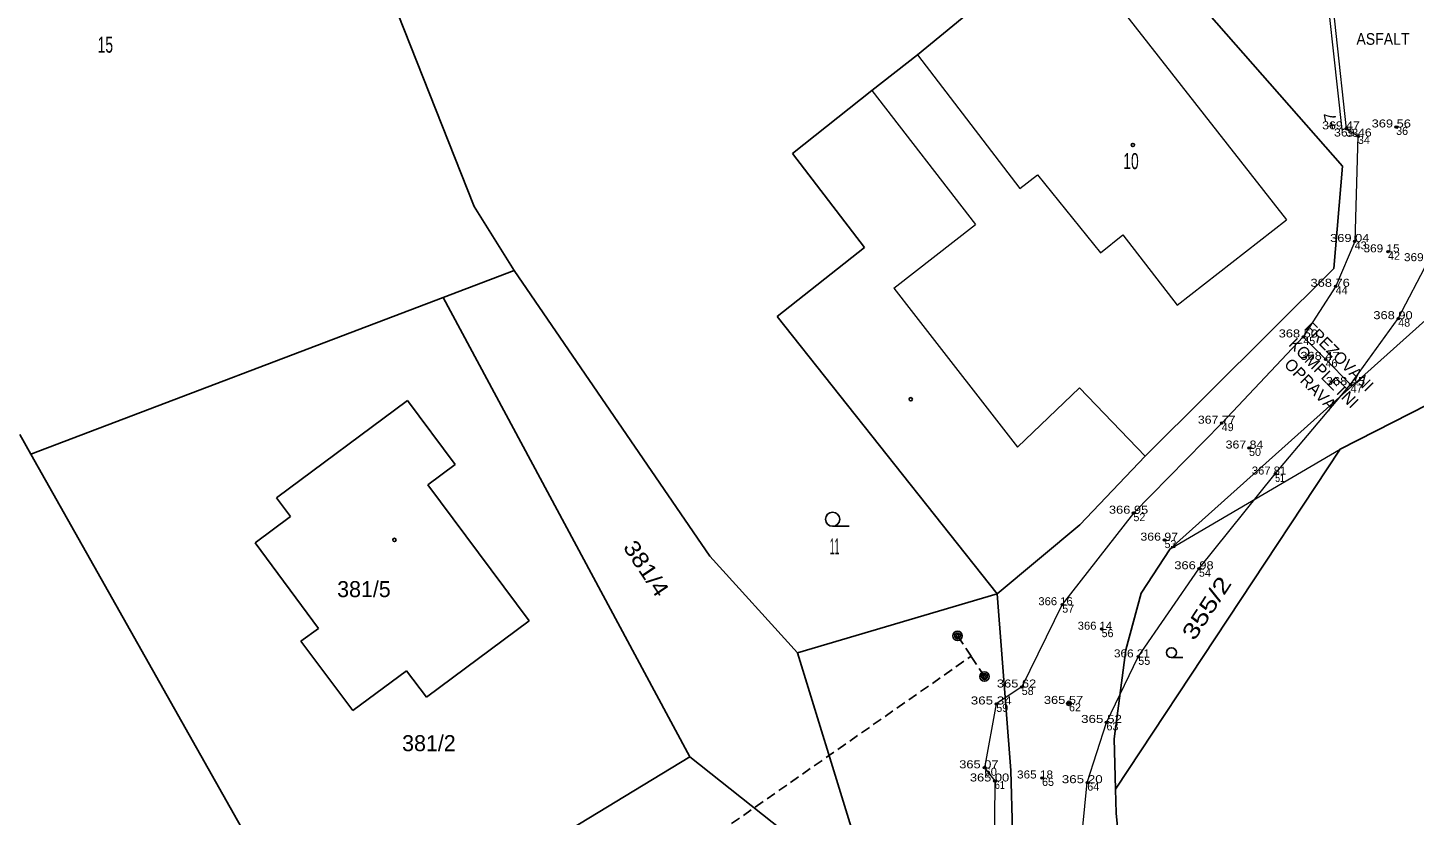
# Model space of a CAD drawing. Extents: x -592965 to -592390, y -1145071 to -1144631.
# Drawn here: x -592704.9 to -592631.3, y -1144835.7 to -1144793.9 of the extents above; entities that cross this region are included whole.
import ezdxf
from ezdxf.enums import TextEntityAlignment as Align

# ---------------------------------------------------------------- set-up
doc = ezdxf.new("R2010")
doc.units = 0
doc.header["$LTSCALE"] = 0.17
doc.header["$PDMODE"] = 32
doc.header["$PDSIZE"] = 0.085
doc.linetypes.add('MEDIUM_DASHED', pattern=[4.5, 3, -1.5])
for name, color, linetype, lineweight in [('1', 7, 'Continuous', 13), ('3', 7, 'Continuous', 13), ('4', 7, 'Continuous', 25)]:
    doc.layers.add(name, color=color, linetype=linetype, lineweight=lineweight)
doc.layers.add('2', color=7, linetype='Continuous')

msp = doc.modelspace()

# ---------------------------------------------------------------- linework, layer by layer
at = {"layer": '1'}
msp.add_line((-592635.14, -1144799.25), (-592634.9, -1144799.22), dxfattribs=at)
for points in [[(-592637.31, -1144779.29), (-592636.24, -1144789.11), (-592635.14, -1144799.25)], [(-592637.07, -1144779.26), (-592636, -1144789.08), (-592634.9, -1144799.22)], [(-592634.9, -1144799.22), (-592634.28, -1144799.6), (-592634.45, -1144805.2), (-592635.46, -1144807.58), (-592637.18, -1144810.27), (-592641.51, -1144814.85)], [(-592641.79, -1144908.72), (-592641.16, -1144902.38), (-592640.38, -1144895.02), (-592640.15, -1144889.82), (-592640.65, -1144883.36), (-592641.29, -1144877.49), (-592642.3, -1144871.74), (-592643.21, -1144867.79), (-592644.53, -1144861.22), (-592645.89, -1144855.01), (-592647.22, -1144849.42), (-592648.49, -1144841.98), (-592649.04, -1144837.88), (-592648.65, -1144833.94), (-592647.63, -1144830.74), (-592645.94, -1144827.26), (-592642.72, -1144822.58), (-592638.67, -1144817.55), (-592634.67, -1144812.8), (-592632.14, -1144809.3), (-592630.54, -1144806.22), (-592629.58, -1144805.74)], [(-592634.67, -1144812.8), (-592636, -1144811.46), (-592637.18, -1144810.27)], [(-592641.51, -1144814.85), (-592646.2, -1144819.63), (-592649.98, -1144824.49), (-592652.13, -1144828.86), (-592653.48, -1144829.76), (-592654.11, -1144833.15), (-592653.56, -1144833.85), (-592653.59, -1144837.97), (-592653.49, -1144842.34), (-592651.91, -1144850.15)]]:
    msp.add_lwpolyline(points, dxfattribs=at)
msp.add_circle((-592649.62, -1144829.73), 0.125, dxfattribs=at)
at = {"layer": '2'}
for p in [(-592632.25, -1144799.12), (-592634.9, -1144799.22), (-592634.28, -1144799.6), (-592634.45, -1144805.2), (-592632.68, -1144805.75), (-592635.46, -1144807.58), (-592632.14, -1144809.3), (-592637.18, -1144810.27), (-592636, -1144811.46), (-592634.67, -1144812.8), (-592641.51, -1144814.85), (-592640.06, -1144816.17), (-592638.67, -1144817.55), (-592646.2, -1144819.63), (-592644.55, -1144821.06), (-592642.72, -1144822.58), (-592649.98, -1144824.49), (-592647.89, -1144825.79), (-592645.94, -1144827.26), (-592652.13, -1144828.86), (-592653.48, -1144829.76), (-592649.62, -1144829.73), (-592647.63, -1144830.74), (-592654.11, -1144833.15), (-592651.05, -1144833.69), (-592653.56, -1144833.85), (-592648.65, -1144833.94)]:
    msp.add_point(p, dxfattribs=at)
at = {"layer": '3'}
for centre, radius in [((-592632.2501, -1144799.1199), 0.0625), ((-592632.2501, -1144799.1199), 0.0395), ((-592632.2501, -1144799.1199), 0.0125), ((-592634.9001, -1144799.2199), 0.0625), ((-592634.9001, -1144799.2199), 0.0395), ((-592634.9001, -1144799.2199), 0.0125), ((-592634.2801, -1144799.5999), 0.0625), ((-592634.2801, -1144799.5999), 0.0395), ((-592634.2801, -1144799.5999), 0.0125), ((-592634.4501, -1144805.1999), 0.0625), ((-592634.4501, -1144805.1999), 0.0395), ((-592634.4501, -1144805.1999), 0.0125), ((-592632.6801, -1144805.7499), 0.0625), ((-592632.6801, -1144805.7499), 0.0395), ((-592632.6801, -1144805.7499), 0.0125), ((-592635.4601, -1144807.5799), 0.0625), ((-592635.4601, -1144807.5799), 0.0395), ((-592635.4601, -1144807.5799), 0.0125), ((-592632.1401, -1144809.2999), 0.0625), ((-592632.1401, -1144809.2999), 0.0395), ((-592632.1401, -1144809.2999), 0.0125), ((-592637.1801, -1144810.2699), 0.0625), ((-592637.1801, -1144810.2699), 0.0395), ((-592637.1801, -1144810.2699), 0.0125), ((-592636.0001, -1144811.4599), 0.0625), ((-592636.0001, -1144811.4599), 0.0395), ((-592636.0001, -1144811.4599), 0.0125), ((-592634.6701, -1144812.7999), 0.0625), ((-592634.6701, -1144812.7999), 0.0395), ((-592634.6701, -1144812.7999), 0.0125), ((-592641.5101, -1144814.8499), 0.0625), ((-592641.5101, -1144814.8499), 0.0395), ((-592641.5101, -1144814.8499), 0.0125), ((-592640.0601, -1144816.1699), 0.0625), ((-592640.0601, -1144816.1699), 0.0395), ((-592640.0601, -1144816.1699), 0.0125), ((-592638.6701, -1144817.5499), 0.0625), ((-592638.6701, -1144817.5499), 0.0395), ((-592638.6701, -1144817.5499), 0.0125), ((-592646.2001, -1144819.6299), 0.0625), ((-592646.2001, -1144819.6299), 0.0395), ((-592646.2001, -1144819.6299), 0.0125), ((-592644.5501, -1144821.0599), 0.0625), ((-592644.5501, -1144821.0599), 0.0395), ((-592644.5501, -1144821.0599), 0.0125), ((-592642.7201, -1144822.5799), 0.0625), ((-592642.7201, -1144822.5799), 0.0395), ((-592642.7201, -1144822.5799), 0.0125), ((-592649.9801, -1144824.4899), 0.0625), ((-592649.9801, -1144824.4899), 0.0395), ((-592649.9801, -1144824.4899), 0.0125), ((-592647.8901, -1144825.7899), 0.0625), ((-592647.8901, -1144825.7899), 0.0395), ((-592647.8901, -1144825.7899), 0.0125), ((-592645.9401, -1144827.2599), 0.0625), ((-592645.9401, -1144827.2599), 0.0395), ((-592645.9401, -1144827.2599), 0.0125), ((-592652.1301, -1144828.8599), 0.0625), ((-592652.1301, -1144828.8599), 0.0395), ((-592652.1301, -1144828.8599), 0.0125), ((-592653.4801, -1144829.7599), 0.0625), ((-592653.4801, -1144829.7599), 0.0395), ((-592653.4801, -1144829.7599), 0.0125), ((-592649.6201, -1144829.7299), 0.0625), ((-592649.6201, -1144829.7299), 0.0395), ((-592649.6201, -1144829.7299), 0.0125), ((-592647.6301, -1144830.7399), 0.0625), ((-592647.6301, -1144830.7399), 0.0395), ((-592647.6301, -1144830.7399), 0.0125), ((-592654.1101, -1144833.1499), 0.0625), ((-592654.1101, -1144833.1499), 0.0395), ((-592654.1101, -1144833.1499), 0.0125), ((-592651.0501, -1144833.6899), 0.0625), ((-592651.0501, -1144833.6899), 0.0395), ((-592651.0501, -1144833.6899), 0.0125), ((-592653.5601, -1144833.8499), 0.0625), ((-592653.5601, -1144833.8499), 0.0395), ((-592653.5601, -1144833.8499), 0.0125), ((-592648.6501, -1144833.9399), 0.0625), ((-592648.6501, -1144833.9399), 0.0395), ((-592648.6501, -1144833.9399), 0.0125)]:
    msp.add_circle(centre, radius, dxfattribs=at)
at = {"layer": '4'}
for p, q in [((-592657.67, -1144795.29), (-592649.93, -1144788.92)), ((-592685.87, -1144791.57), (-592681.2, -1144803.34)), ((-592660.09, -1144797.18), (-592657.67, -1144795.29)), ((-592664.31, -1144800.54), (-592660.09, -1144797.18)), ((-592664.31, -1144800.54), (-592660.48, -1144805.53)), ((-592635.55, -1144806.64), (-592635.1, -1144801.2)), ((-592681.2, -1144803.34), (-592679.08, -1144806.74)), ((-592665.11, -1144809.19), (-592660.48, -1144805.53)), ((-592682.86, -1144808.18), (-592679.08, -1144806.74)), ((-592679.08, -1144806.74), (-592668.69, -1144821.92)), ((-592645.57, -1144816.6), (-592635.55, -1144806.64)), ((-592704.74, -1144816.49), (-592682.86, -1144808.18)), ((-592682.86, -1144808.18), (-592671.64, -1144829.05)), ((-592665.11, -1144809.19), (-592653.43, -1144823.92)), ((-592644.25, -1144821.53), (-592630.7, -1144809.39)), ((-592635.23, -1144816.23), (-592628.66, -1144812.88)), ((-592691.7, -1144818.81), (-592684.75, -1144813.64)), ((-592684.75, -1144813.64), (-592682.21, -1144817.05)), ((-592705.33, -1144815.45), (-592704.74, -1144816.49)), ((-592704.74, -1144816.49), (-592691.02, -1144840.81)), ((-592649.04, -1144820.25), (-592645.57, -1144816.6)), ((-592647.16, -1144834.28), (-592635.23, -1144816.23)), ((-592683.66, -1144818.12), (-592682.21, -1144817.05)), ((-592683.66, -1144818.12), (-592678.29, -1144825.34)), ((-592691.7, -1144818.81), (-592690.96, -1144819.81)), ((-592692.84, -1144821.21), (-592690.96, -1144819.81)), ((-592661.295, -1144820.33), (-592662.17, -1144820.33)), ((-592653.43, -1144823.92), (-592649.04, -1144820.25)), ((-592692.84, -1144821.21), (-592689.47, -1144825.75)), ((-592668.69, -1144821.92), (-592664.03, -1144827.05)), ((-592664.03, -1144827.05), (-592653.43, -1144823.92)), ((-592653.43, -1144823.92), (-592652.71, -1144833.3)), ((-592683.74, -1144829.4), (-592678.29, -1144825.34)), ((-592690.4, -1144826.43), (-592689.47, -1144825.75)), ((-592690.4, -1144826.43), (-592687.64, -1144830.11)), ((-592664.03, -1144827.05), (-592661.12, -1144836.54)), ((-592647.23, -1144831.62), (-592646.61, -1144826.89)), ((-592643.568, -1144827.3), (-592644.18, -1144827.3)), ((-592687.64, -1144830.11), (-592684.79, -1144828)), ((-592684.79, -1144828), (-592683.74, -1144829.4)), ((-592671.64, -1144829.05), (-592669.75, -1144832.57)), ((-592647.23, -1144831.62), (-592647.16, -1144834.28)), ((-592689.08, -1144844.27), (-592669.75, -1144832.57)), ((-592669.75, -1144832.57), (-592663.06, -1144837.87))]:
    msp.add_line(p, q, dxfattribs=at)
at = {"layer": '4', "lineweight": 13}
for p, q in [((-592649.93, -1144788.92), (-592638.07, -1144804.05)), ((-592657.67, -1144795.29), (-592652.24, -1144802.39)), ((-592660.09, -1144797.18), (-592654.58, -1144804.3)), ((-592643.87, -1144808.59), (-592638.07, -1144804.05)), ((-592658.93, -1144807.69), (-592654.58, -1144804.3)), ((-592647.94, -1144805.8), (-592646.77, -1144804.85)), ((-592646.77, -1144804.85), (-592643.87, -1144808.59)), ((-592652.35, -1144816.13), (-592649.07, -1144812.97)), ((-592649.07, -1144812.97), (-592645.57, -1144816.6)), ((-592644.25, -1144821.53), (-592635.23, -1144816.23))]:
    msp.add_line(p, q, dxfattribs=at)
at = {"layer": '4'}
for points in [[(-592647.73, -1144786.83), (-592647.46, -1144787.13), (-592635.1, -1144801.2)], [(-592646.61, -1144826.89), (-592645.79, -1144823.88), (-592644.25, -1144821.53)], [(-592652.71, -1144833.3), (-592652.44, -1144842.96), (-592646.69, -1144839.87)], [(-592647.16, -1144834.28), (-592647.12, -1144835.56), (-592646.69, -1144839.87)]]:
    msp.add_lwpolyline(points, dxfattribs=at)
at = {"layer": '4', "lineweight": 13}
for points in [[(-592652.24, -1144802.39), (-592651.29, -1144801.66), (-592647.94, -1144805.8)], [(-592658.93, -1144807.69), (-592657.88, -1144809.03), (-592652.35, -1144816.13)]]:
    msp.add_lwpolyline(points, dxfattribs=at)
at = {"layer": '4', "linetype": 'MEDIUM_DASHED'}
for points in [[(-592654.11, -1144828.31), (-592654.82, -1144827.23), (-592655.54, -1144826.15)], [(-592721.92, -1144873.86), (-592691.99, -1144853.21), (-592654.82, -1144827.23)]]:
    msp.add_lwpolyline(points, dxfattribs=at)
at = {"layer": '4'}
for centre, radius in [((-592646.23, -1144800.08), 0.0875), ((-592658.02, -1144813.58), 0.0875), ((-592662.17, -1144819.955), 0.375), ((-592685.44, -1144821.05), 0.0875), ((-592655.54, -1144826.15), 0.25), ((-592655.54, -1144826.15), 0.15), ((-592655.54, -1144826.15), 0.075), ((-592644.18, -1144827.0375), 0.2625), ((-592654.11, -1144828.31), 0.25), ((-592654.11, -1144828.31), 0.15), ((-592654.11, -1144828.31), 0.075)]:
    msp.add_circle(centre, radius, dxfattribs=at)

# ---------------------------------------------------------------- texts
at = {"layer": '1', "width": 0.9}
msp.add_text('ASFALT', height=0.62, dxfattribs=at).set_placement((-592632.95, -1144794.76), align=Align.CENTER)
at = {"layer": '1'}
for s, rotation, p in [('+7', 101.437, (-592635.4088, -1144798.7665)), ('FREZOVANI', 314.785, (-592635.5023, -1144811.5371)), ('KOMPLETNI', 314.785, (-592636.3125, -1144812.4071)), ('OPRAVA', 314.785, (-592637.0228, -1144813.0071))]:
    msp.add_text(s, height=0.62, rotation=rotation, dxfattribs=at).set_placement(p, align=Align.CENTER)
at = {"layer": '2'}
for s, p in [('36', (-592632.25, -1144799.545)), ('33', (-592634.9, -1144799.645)), ('34', (-592634.28, -1144800.025)), ('43', (-592634.45, -1144805.625)), ('42', (-592632.68, -1144806.175)), ('44', (-592635.46, -1144808.005)), ('48', (-592632.14, -1144809.725)), ('45', (-592637.18, -1144810.695)), ('46', (-592636, -1144811.885)), ('47', (-592634.67, -1144813.225)), ('49', (-592641.51, -1144815.275)), ('50', (-592640.06, -1144816.595)), ('52', (-592646.2, -1144820.055)), ('53', (-592644.55, -1144821.485)), ('54', (-592642.72, -1144823.005)), ('57', (-592649.98, -1144824.915)), ('56', (-592647.89, -1144826.215)), ('55', (-592645.94, -1144827.685)), ('58', (-592652.13, -1144829.285)), ('59', (-592653.48, -1144830.185)), ('62', (-592649.62, -1144830.155)), ('63', (-592647.63, -1144831.165)), ('65', (-592651.05, -1144834.115)), ('64', (-592648.65, -1144834.365))]:
    msp.add_text(s, height=0.425, dxfattribs=at).set_placement(p)
for s, width, p in [('51', 0.8, (-592638.67, -1144817.975)), ('60', 1.05, (-592654.11, -1144833.575)), ('61', 0.85, (-592653.56, -1144834.275))]:
    msp.add_text(s, height=0.425, dxfattribs=dict(at, width=width)).set_placement(p)
at = {"layer": '3'}
for s, width, p in [('369 47', 1.15, (-592635.1795, -1144799.25)), ('369 56', 1.2, (-592632.508, -1144799.15)), ('369 46', 1.15, (-592634.5495, -1144799.63)), ('369 04', 1.2, (-592634.713, -1144805.23)), ('369 15', 1.1, (-592633.025, -1144805.78)), ('369 21', 1.1, (-592630.878, -1144806.25)), ('368 76', 1.2, (-592635.753, -1144807.61)), ('368 90', 1.2, (-592632.4165, -1144809.33)), ('368 50', 1.2, (-592637.4445, -1144810.3)), ('368 47', 1.2, (-592636.293, -1144811.49)), ('368 45', 1.2, (-592634.9415, -1144812.83)), ('367 77', 1.15, (-592641.7795, -1144814.88)), ('367 84', 1.15, (-592640.303, -1144816.2)), ('367 81', 1.05, (-592639, -1144817.58)), ('366 95', 1.2, (-592646.458, -1144819.66)), ('366 97', 1.15, (-592644.8295, -1144821.09)), ('366 98', 1.2, (-592642.9845, -1144822.61)), ('366 16', 1.05, (-592650.3365, -1144824.52)), ('366 14', 1.05, (-592648.2465, -1144825.82)), ('366 21', 1.1, (-592646.278, -1144827.29)), ('365 62', 1.2, (-592652.4045, -1144828.89)), ('365 34', 1.25, (-592653.7515, -1144829.79)), ('365 57', 1.2, (-592649.9115, -1144829.76)), ('365 52', 1.25, (-592647.893, -1144830.77)), ('365 07', 1.2, (-592654.4065, -1144833.18)), ('365 00', 1.2, (-592653.8395, -1144833.88)), ('365 18', 1.1, (-592651.425, -1144833.72)), ('365 20', 1.25, (-592648.918, -1144833.97))]:
    msp.add_text(s, height=0.425, dxfattribs=dict(at, width=width)).set_placement(p, align=Align.CENTER)
at = {"layer": '4'}
for s, width, p in [('15', 0.65, (-592701.2, -1144795.18)), ('10', 0.65, (-592646.74, -1144801.36)), ('11', 0.4, (-592662.32, -1144821.82))]:
    msp.add_text(s, height=0.85, dxfattribs=dict(at, width=width)).set_placement(p)
for s, rotation, width, p in [('381/4', 303.69, 1.15, (-592673.33, -1144821.44)), ('355/2', 56.835, 1.3, (-592642.97, -1144826.45))]:
    msp.add_text(s, height=0.85, rotation=rotation, dxfattribs=dict(at, width=width)).set_placement(p)
for s, p in [('381/5', (-592688.48, -1144824.09)), ('381/2', (-592685.03, -1144832.27))]:
    msp.add_text(s, height=0.85, dxfattribs=at).set_placement(p)

doc.saveas('drawing.dxf')
